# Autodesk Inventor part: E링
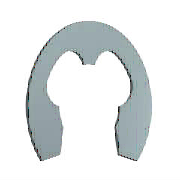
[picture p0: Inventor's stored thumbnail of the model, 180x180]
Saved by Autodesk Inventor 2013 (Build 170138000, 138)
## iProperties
Created: 2012-02
Part Number: E링
Material: 강철, 연강
Description: 스프링 리테이닝 링
Document SubType Name: Modeling
Standard: JIS B 2805
Designer: mduedu
Standards Organization: JIS
Language: ko-KR
Size Designation: 4
Categories: <MemberInstance><Categories><Category DisplayName="샤프트 부품" InternalName="7f7aeb1f-a693-4053-b835-cee3144e0d98" Mnemonic="SHFT"><Category DisplayName="써클립" Inter
Density: 1 g/cm^3
IsCustomPart: 1
Author: mduedu
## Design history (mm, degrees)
sketch "스케치1"
  geometry: L1 (-0.4, 0.024)-(0, 0.024) reference; L2 (-3.206, 0)-(3.486, 0) reference; L3 (-1.833, -3.276)-(1.833, -3.276); L4 (0, 1.949)-(0, -3.479) reference; L5 (-2.4, -1.676)-(-2.008, -1.676); L6 (-0.4, -0.076)-(-0.4, 0.312); L7 (0, 2.024)-(2.53, 2.024); L8 (-1.833, -3.276)-(-2.47, -5.119); L9 (0, -0.476)-(-1.278, -0.476); L10 (1.833, -3.276)-(2.47, -5.119); L11 (2.4, -1.676)-(2.008, -1.676); L12 (0.4, -0.076)-(0.4, 0.312); C1 r 2.5 at (0, -2.476); A1 r 2 centre (0, -2.476) between (-1.894, -1.835) and (-1.833, -3.276); A2 r 0.4 centre (0, -0.076) between (-0.4, -0.076) and (0.4, -0.076); A3 r 4.5 centre (0, -2.476) between (3.505, -5.299) and (-3.505, -5.299); A4 r 3.2 centre (0, -2.476) between (-0.8, 0.622) and (-2.824, -0.97); A5 r 0.32 centre (-0.72, 0.312) between (-0.4, 0.312) and (-0.8, 0.622); A6 r 0.48 centre (-2.4, -1.196) between (-2.824, -0.97) and (-2.4, -1.676); A7 r 0.12 centre (-2.008, -1.796) between (-1.894, -1.835) and (-2.008, -1.676); A8 r 0.6 centre (-3.037, -4.923) between (-3.505, -5.299) and (-2.47, -5.119); A9 r 0.6 centre (3.037, -4.923) between (2.47, -5.119) and (3.505, -5.299); A10 r 2 centre (0, -2.476) between (1.833, -3.276) and (1.894, -1.835); A11 r 0.12 centre (2.008, -1.796) between (2.008, -1.676) and (1.894, -1.835); A12 r 0.48 centre (2.4, -1.196) between (2.4, -1.676) and (2.824, -0.97); A13 r 3.2 centre (0, -2.476) between (2.824, -0.97) and (0.8, 0.622); A14 r 0.32 centre (0.72, 0.312) between (0.8, 0.622) and (0.4, 0.312); 1 further point
  constraints: 30 point on circle, 20 end point, 15 centre point, 13 symmetric about line, 12 tangent, 8 point on line, 4 parallel, 2 coincident, 2 horizontal, 1 concentric, 1 perpendicular, 1 vertical alignment, 9 other
  dimensions: "d0" = 5 diameter of C1 (= WD); "d3" = 0.8 distance from line of A1.centre L3 (= 0.2 x ND); "d4" = 0.4 radius of A2 (= 0.1 x ND); "d5" = 9 diameter of A3 (= SD2); "d8" = 3.2 radius of A4 (= 0.8 x ND); "d9" = 0.8 distance from line of A1.centre L5 (= 0.2 x ND); "d10" = 0.32 radius of A5 (= 0.08 x ND); "d11" = 0.48 radius of A6 (= 0.12 x ND); "d12" = 0.12 radius of A7 (= 0.03 x ND); "d13" = 0.6 radius of A8 (= 0.15 x ND); "d14" = 2 distance from line of A1.centre L9 (= 0.5 x ND); "d15" = 2 radius of A1 (= 0.5 x ND)
extrude "본체" new body sketch "스케치1" distance "d16" = 0.6 (= SD); taper "d17" = 0 deg
workaxis "Work Axis1"
workaxis "Work Axis2"
workplane "Work Plane1"
body "Solid1"
other parameters: "ND" = 4 [user parameter; used in 14 equation terms], "SD" = 0.6 [user parameter; used in 1 equation term], "WD" = 5 (= WDMIN) [user parameter; used in 1 equation term], "d1" = 6.4 (= 1.6 x ND), "d2" = 4 (= ND), "SD2" = 9 [user parameter; used in 1 equation term], "d6" = 4 (= ND), "d7" = 0.6 (= 0.15 x ND), "d18" = 0, "d19" = 0, "d27" = 0, "d28" = 0, "WDMIN" = 5 [user parameter; used in 1 equation term], "SNB" = 0.7 [user parameter], "WDMAX" = 7 [user parameter], "BUBRMI" = 1.2 [user parameter]
